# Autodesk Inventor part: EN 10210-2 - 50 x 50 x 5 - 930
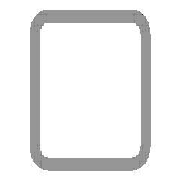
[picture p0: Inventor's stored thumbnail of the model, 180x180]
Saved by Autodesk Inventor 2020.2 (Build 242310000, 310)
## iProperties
IsCustomPart: 1
_CCFamilyMember: 16
_CCFamilyDisplayName: DIN EN 10210-2 (USAS B17.1 quadratisch) - Rohrleitung — In Klammern angegebene Größen wurden aufgehoben
_FrameMemberDoc: Frame Member File
_Version: 15.0.0
_GetPNFromCC: 1
Created: 2019-10
Part Number: EN 10210-2 - 50 x 50 x 5 - 930
Material: Stahl, weich
Description: Rohrleitung
Document SubType Name: Modeling
Standard: DIN
Designer: lutzd
Standard Revision: 2006-07
Standards Organization: DIN
Language: de-DE
Size Designation: 50 x 50 x 5
Categories: <MemberInstance><Categories><Category DisplayName="Profile" InternalName="089c4875-fa83-4c05-b084-43b9cc11f5ed" Mnemonic="GRDR"><CategoryParameter DisplayName="
Stock Number: 50 x 50 x 5
Mass: 6374.61 g
Surface Area: 3165.88 cm^2
Volume: 812.053 cm^3
Density: 7.85 g/cm^3
Appearance: Semi-Polished(8)
G_L: 930,000 mm
G_W: 50,000 mm
G_H: 50,000 mm
Dimensions: 50x50x930 mm
Mass: 6,375 kg
DocNumber: ADSK-014296
Folder: .
+823E290F-38FE-4FB3-A8E0-34631DA734AF+SCHNITTDETAIL1: Schnittwinkel 90,00 grd
+48875C2F-1EEB-4620-AD6D-771643C7740F+SCHNITTDETAIL2: Schnittwinkel 90,00 grd
VLT_Material: Stahl, weich
Title: Profil-Bauteil
Author: lutzd
Revision Number: -
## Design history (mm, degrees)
node "Startebene"
node "Endebene"
sketch "Skizze"
  geometry: L1 (-25, -17.5)-(-25, 17.5); L2 (-17.5, 25)-(17.5, 25); L3 (25, 17.5)-(25, -17.5); L4 (17.5, -25)-(-17.5, -25); L5 (-15, 20)-(15, 20); L6 (20, 15)-(20, -15); L7 (15, -20)-(-15, -20); L8 (-20, -15)-(-20, 15); L9 (0, 37.175)-(0, -37.175) reference; L10 (-37.175, 0)-(37.175, 0) reference; A1 r 7.5 centre (-17.5, -17.5) between (-25, -17.5) and (-17.5, -25); A2 r 7.5 centre (-17.5, 17.5) between (-17.5, 25) and (-25, 17.5); A3 r 7.5 centre (17.5, 17.5) between (25, 17.5) and (17.5, 25); A4 r 7.5 centre (17.5, -17.5) between (17.5, -25) and (25, -17.5); A5 r 5 centre (-15, -15) between (-20, -15) and (-15, -20); A6 r 5 centre (-15, 15) between (-15, 20) and (-20, 15); A7 r 5 centre (15, 15) between (20, 15) and (15, 20); A8 r 5 centre (15, -15) between (15, -20) and (20, -15)
  constraints: 16 end point, 16 point on circle, 16 tangent, 8 centre point, 6 equal radius, 4 parallel, 2 perpendicular, 2 other
  dimensions: "d7" = 7.5 radius of A1 (= G_IR); "d10" = 50 distance between parallel lines of L2 L4 (= G_H); "d11" = 50 distance between parallel lines of L1 L3 (= G_W); "d12" = 5 distance between parallel lines of L3 L6 (= G_T); "d15" = 25 distance between parallel lines of L2 L10 (= 0.5 x d10); "d16" = 25 distance between parallel lines of L9 L3 (= 0.5 x d11); "d19" = 5 radius of A5 (= G_T); "d20" = 5 distance between parallel lines of L4 L7 (= G_T)
extrude "Körper" new body sketch "Skizze" stored distance "d3" = 930 (= G_L); taper "d4" = 0 deg
node "Driven Length"
  sketch "Sketch3"
    geometry: L1 (0, 0)-(10, 0) reference
    constraints: 2 end point, 1 horizontal
  workplane "Work Plane3"
  sketch "Sketch4"
    geometry: L1 (-2, 50)-(12, 50) reference; L2 (-2, 980)-(12, 980) reference
    dimensions: "d18" = 930 distance between parallel lines of L1 L2 (derived)
workplane "Arbeitsebene4"
feature "Trennen1"
workplane "Arbeitsebene5"
feature "Trennen2"
body "Solid1"
other parameters: "G_W" = 50 [user parameter; used in 1 equation term], "G_H" = 50 [user parameter; used in 1 equation term], "G_T" = 5 [user parameter; used in 3 equation terms], "G_IR" = 7.5 [user parameter; used in 1 equation term], "G_L" = 930 (= d18) [user parameter; used in 1 equation term], "d17" = 90 deg
